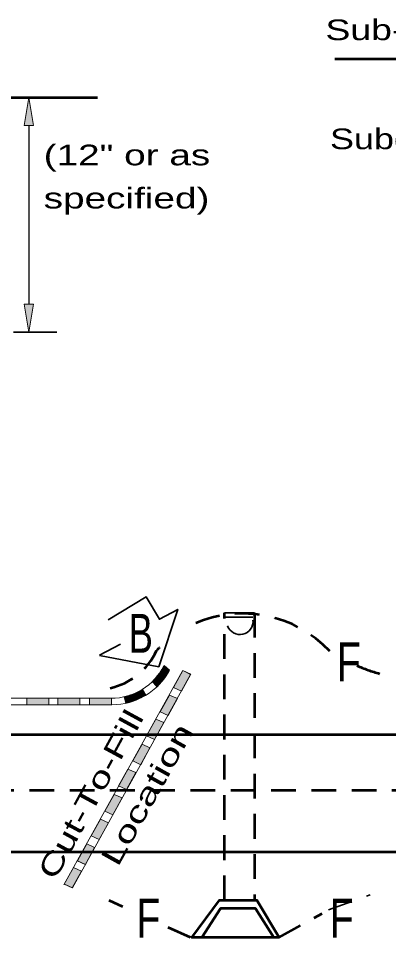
# Model space of a CAD drawing. Extents: x 36 to 71.3, y 0.3 to 22.3.
# Drawn here: x 43.4 to 45.78, y 10.76 to 16.68 of the extents above; entities that cross this region are included whole.
import ezdxf

# ---------------------------------------------------------------- set-up
doc = ezdxf.new("R2010")
doc.units = 0
doc.header["$LTSCALE"] = 0.053
doc.linetypes.add('MEDIUM_DASHED', pattern=[4.5, 3, -1.5])
for name, color, linetype, lineweight in [('1', 7, 'Continuous', 13), ('2', 7, 'Continuous', 13), ('3', 7, 'MEDIUM_DASHED', 53), ('4', 7, 'Continuous', 13)]:
    doc.layers.add(name, color=color, linetype=linetype, lineweight=lineweight)

msp = doc.modelspace()

# ---------------------------------------------------------------- hatches: boundary and pattern name
at = {"layer": '1'}
for points in [[(43.44075, 15.98875), (43.50075, 15.98875), (43.47075, 16.16875), (43.47075, 16.16875)], [(43.44075, 14.838), (43.50075, 14.838), (43.47075, 14.658), (43.47075, 14.658)], [(44.31433, 12.4685), (44.33075, 12.49658), (44.36758, 12.47083), (44.34825, 12.4405)], [(44.33075, 12.49542), (44.33942, 12.51183), (44.37458, 12.48317), (44.36817, 12.47142)], [(44.26525, 12.40958), (44.29333, 12.43992), (44.32483, 12.41017), (44.29392, 12.37617)], [(44.29275, 12.44342), (44.31317, 12.46792), (44.34883, 12.4405), (44.32483, 12.41017)], [(44.39958, 12.37225), (44.45975, 12.47992), (44.51067, 12.45683), (44.45108, 12.348)], [(44.08283, 12.31192), (44.11733, 12.32067), (44.12783, 12.27858), (44.09392, 12.26983)], [(44.11783, 12.32125), (44.14533, 12.33117), (44.16, 12.29025), (44.12842, 12.27858)], [(44.14533, 12.33058), (44.1745, 12.34525), (44.18975, 12.30367), (44.16175, 12.29083)], [(44.17575, 12.34467), (44.19983, 12.35867), (44.222, 12.32125), (44.191, 12.30425)], [(44.31433, 12.21483), (44.37442, 12.32242), (44.42542, 12.29942), (44.36575, 12.19058)], [(43.45725, 12.25992), (43.59875, 12.25992), (43.59875, 12.30192), (43.45725, 12.30192)], [(43.65717, 12.25992), (43.79858, 12.25992), (43.79858, 12.30192), (43.65717, 12.30192)], [(43.85992, 12.25992), (44.00133, 12.25992), (44.00133, 12.30192), (43.85992, 12.30192)], [(44.22592, 12.06042), (44.286, 12.16808), (44.337, 12.145), (44.27733, 12.03625)], [(44.13742, 11.89833), (44.19758, 12.006), (44.2485, 11.98292), (44.18892, 11.87408)], [(44.04692, 11.73858), (44.10692, 11.84625), (44.15792, 11.82317), (44.09825, 11.71433)], [(43.95842, 11.57575), (44.01858, 11.68333), (44.0695, 11.66033), (44.00992, 11.5515)], [(43.86992, 11.41592), (43.93017, 11.52358), (43.98108, 11.5005), (43.9215, 11.39175)], [(43.78158, 11.25617), (43.84167, 11.36383), (43.89267, 11.34075), (43.833, 11.23192)], [(43.69733, 11.10492), (43.7575, 11.2125), (43.80833, 11.1895), (43.74883, 11.08067)]]:
    msp.add_hatch(color=256, dxfattribs=at).paths.add_polyline_path(points)

# ---------------------------------------------------------------- linework, layer by layer
at = {"layer": '1', "lineweight": 53}
for p, q in [((45.43675, 16.419), (46.67633, 16.419)), ((42.81908, 16.16875), (43.91108, 16.16875)), ((39.79458, 12.068), (49.87267, 12.068)), ((39.77025, 11.31333), (49.87267, 11.31333))]:
    msp.add_line(p, q, dxfattribs=at)
at = {"layer": '1'}
for p, q in [((43.40375, 16.16875), (43.65075, 16.16875)), ((44.37442, 12.48292), (44.34142, 12.51092)), ((43.6955, 11.10183), (44.45592, 12.47508)), ((44.29258, 12.377), (44.26267, 12.41058)), ((44.09367, 12.27), (44.08233, 12.31017)), ((44.22225, 12.32167), (44.20075, 12.35825)), ((44.00117, 12.26017), (41.44908, 12.26017)), ((43.99767, 12.30217), (41.45258, 12.30217)), ((43.78125, 11.25542), (43.83158, 11.2325))]:
    msp.add_line(p, q, dxfattribs=at)
at = {"layer": '1', "lineweight": 25}
msp.add_line((43.47075, 15.98875), (43.47075, 14.838), dxfattribs=at)
at = {"layer": '1', "lineweight": 35}
for p, q in [((43.37108, 14.658), (43.65075, 14.658)), ((44.72858, 12.85192), (44.91958, 12.85192)), ((44.73383, 12.824), (44.91092, 12.824)), ((43.92383, 12.57858), (44.05817, 12.64958)), ((44.30633, 12.50508), (43.92433, 12.577))]:
    msp.add_line(p, q, dxfattribs=at)
at = {"layer": '1'}
for points in [[(43.44075, 15.98875), (43.50075, 15.98875), (43.47075, 16.16875), (43.47075, 16.16875)], [(43.44075, 14.838), (43.50075, 14.838), (43.47075, 14.658), (43.47075, 14.658)], [(44.31433, 12.4685), (44.33075, 12.49658), (44.36758, 12.47083), (44.34825, 12.4405)], [(44.33075, 12.49542), (44.33942, 12.51183), (44.37458, 12.48317), (44.36817, 12.47142)], [(44.26525, 12.40958), (44.29333, 12.43992), (44.32483, 12.41017), (44.29392, 12.37617)], [(44.29275, 12.44342), (44.31317, 12.46792), (44.34883, 12.4405), (44.32483, 12.41017)], [(44.39958, 12.37225), (44.45975, 12.47992), (44.51067, 12.45683), (44.45108, 12.348)], [(44.08283, 12.31192), (44.11733, 12.32067), (44.12783, 12.27858), (44.09392, 12.26983)], [(44.11783, 12.32125), (44.14533, 12.33117), (44.16, 12.29025), (44.12842, 12.27858)], [(44.14533, 12.33058), (44.1745, 12.34525), (44.18975, 12.30367), (44.16175, 12.29083)], [(44.17575, 12.34467), (44.19983, 12.35867), (44.222, 12.32125), (44.191, 12.30425)], [(44.31433, 12.21483), (44.37442, 12.32242), (44.42542, 12.29942), (44.36575, 12.19058)], [(43.45725, 12.25992), (43.59875, 12.25992), (43.59875, 12.30192), (43.45725, 12.30192)], [(43.65717, 12.25992), (43.79858, 12.25992), (43.79858, 12.30192), (43.65717, 12.30192)], [(43.85992, 12.25992), (44.00133, 12.25992), (44.00133, 12.30192), (43.85992, 12.30192)], [(44.22592, 12.06042), (44.286, 12.16808), (44.337, 12.145), (44.27733, 12.03625)], [(44.13742, 11.89833), (44.19758, 12.006), (44.2485, 11.98292), (44.18892, 11.87408)], [(44.04692, 11.73858), (44.10692, 11.84625), (44.15792, 11.82317), (44.09825, 11.71433)], [(43.95842, 11.57575), (44.01858, 11.68333), (44.0695, 11.66033), (44.00992, 11.5515)], [(43.86992, 11.41592), (43.93017, 11.52358), (43.98108, 11.5005), (43.9215, 11.39175)], [(43.78158, 11.25617), (43.84167, 11.36383), (43.89267, 11.34075), (43.833, 11.23192)], [(43.69733, 11.10492), (43.7575, 11.2125), (43.80833, 11.1895), (43.74883, 11.08067)]]:
    msp.add_lwpolyline(points, close=True, dxfattribs=at)
at = {"layer": '1', "lineweight": 35}
msp.add_lwpolyline([(43.979, 12.806), (44.22508, 12.9545), (44.30892, 12.81025), (44.42708, 12.87358), (44.30633, 12.50508)], dxfattribs=at)
at = {"layer": '1'}
msp.add_lwpolyline([(43.69908, 11.10458), (43.74942, 11.08167), (44.50983, 12.45492), (44.47167, 12.474)], dxfattribs=at)
at = {"layer": '1', "lineweight": 53}
msp.add_lwpolyline([(45.07925, 10.76225), (44.51675, 10.76225), (44.69558, 11.0015), (44.93517, 11.0015)], close=True, dxfattribs=at)
msp.add_lwpolyline([(45.04458, 10.761), (44.9265, 10.94808), (44.70258, 10.94808), (44.581, 10.761)], dxfattribs=at)
at = {"layer": '1', "lineweight": 35}
msp.add_arc((44.82708, 12.79625), 0.08426, 199.59098, 5.89577, dxfattribs=at)
at = {"layer": '1'}
for centre, radius, end in [((43.99908, 12.68258), 0.38063, 333.14136), ((44.00275, 12.68208), 0.42212, 331.76717)]:
    msp.add_arc(centre, radius, 270, end, dxfattribs=at)
at = {"layer": '3'}
for p, q in [((44.72858, 11.0015), (44.72858, 12.85192)), ((44.91958, 12.85192), (44.91958, 10.99767)), ((49.84833, 11.70783), (39.77025, 11.70783)), ((44.07425, 10.95975), (43.9855, 11.00025)), ((45.07758, 10.76225), (45.35483, 10.91692)), ((44.50983, 10.761), (44.29817, 10.85758))]:
    msp.add_line(p, q, dxfattribs=at)
at = {"layer": '3', "lineweight": 35}
msp.add_line((45.397, 10.94042), (45.66433, 11.03717), dxfattribs=at)
at = {"layer": '3'}
for centre, radius, start, end in [((44.84575, 12.08275), 0.76447, 43.09637, 113.92976), ((43.89683, 12.79042), 0.43403, 282.72731, 335.27174), ((44.84575, 12.08275), 0.76447, 134.59921, 136.51049), ((46.04717, 13.60092), 1.18554, 237.14247, 237.14505), ((46.04717, 13.60092), 1.18554, 246.66529, 254.23818)]:
    msp.add_arc(centre, radius, start, end, dxfattribs=at)
at = {"layer": '4'}
msp.add_line((43.47075, 14.658), (43.47083, 14.658), dxfattribs=at)

# ---------------------------------------------------------------- texts
at = {"layer": '2'}
for s, height, width, p in [('Sub-base', 0.133, 1.35, (45.37683, 16.53875)), ('Subgrade', 0.133, 1.3, (45.40592, 15.83675)), ('(12" or as', 0.133, 1.4, (43.565, 15.73292)), ('specified)', 0.133, 1.4, (43.565, 15.45508)), ('B', 0.25, 0.7, (44.11142, 12.59492)), ('F', 0.25, 0.75, (45.45058, 12.41158)), ('F', 0.25, 0.75, (44.16225, 10.7615)), ('F', 0.25, 0.75, (45.40525, 10.7615))]:
    msp.add_text(s, height=height, dxfattribs=dict(at, width=width)).set_placement(p)
for s, rotation, width, p in [('Cut-To-Fill', 61.44, 1.45, (43.6385, 11.12358)), ('Location', 60.85, 1.5, (44.04167, 11.2105))]:
    msp.add_text(s, height=0.133, rotation=rotation, dxfattribs=dict(at, width=width)).set_placement(p)

doc.saveas('drawing.dxf')
